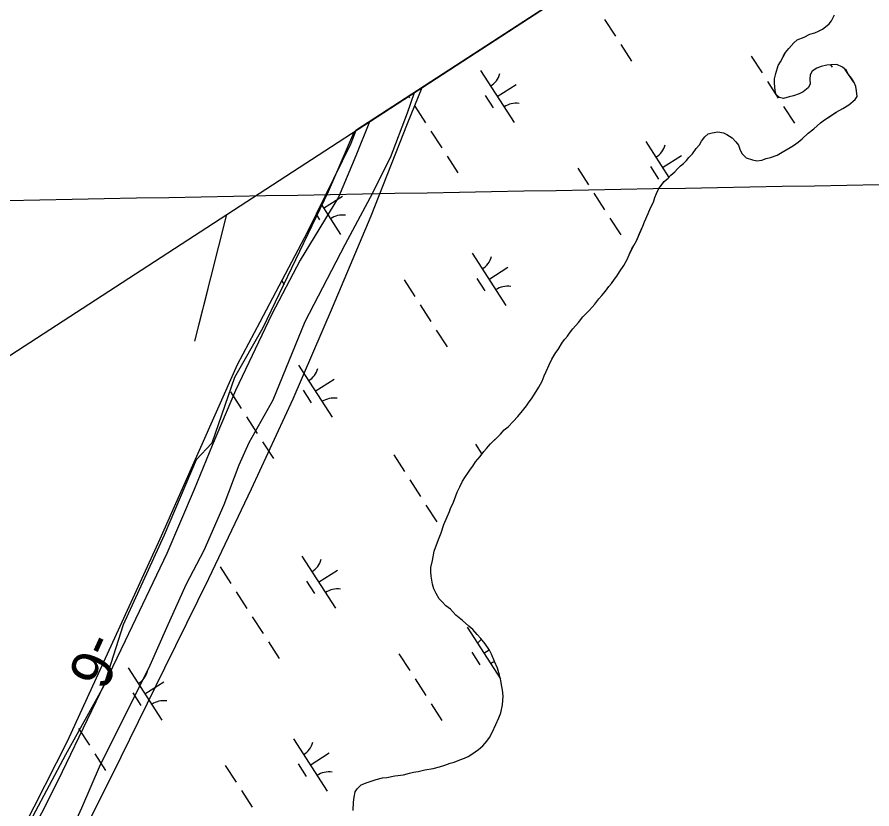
# Model space of a CAD drawing. Extents: x 3937982 to 3958556, y 219448 to 241894.
# Drawn here: x 3943922 to 3944611, y 235847 to 236485 of the extents above; entities that cross this region are included whole.
import ezdxf

# ---------------------------------------------------------------- set-up
doc = ezdxf.new("R2010")
doc.units = 0
for name, color, linetype in [('V-GRID-FRAM', 7, 'Continuous'), ('V-GRID-MAJR', 7, 'Continuous'), ('V-RIVR-EDGE', 7, 'Continuous'), ('V-RIVR-JETY', 7, 'Continuous'), ('V-RIVR-RANG', 7, 'Continuous'), ('V-RRAP-FSHR', 7, 'Continuous'), ('V-TOPO-MINR', 7, 'Continuous'), ('V-TOPO-SHOR', 7, 'Continuous'), ('V-WETL-SWMP', 7, 'Continuous')]:
    doc.layers.add(name, color=color, linetype=linetype)

msp = doc.modelspace()

# ---------------------------------------------------------------- linework, layer by layer
at = {"layer": 'V-GRID-FRAM'}
msp.add_lwpolyline([(3948998.173, 239513.74), (3957109.469, 226912.286), (3949780.097, 222173.81), (3941699.799, 234772.334), (3948998.173, 239513.74)], dxfattribs=at)
at = {"layer": 'V-GRID-MAJR'}
msp.add_spline([(3942640.453, 236314.075), (3945968.142, 236374.431), (3951288.627, 236471.56), (3951347.833, 236472.645)], degree=3, dxfattribs=at)
at = {"layer": 'V-RIVR-EDGE'}
msp.add_lwpolyline([(3944193.63, 236392.457), (3944193.155, 236391.169), (3944172.689, 236343.94), (3944119.949, 236234.524), (3944097.121, 236194.379), (3944079.017, 236141.639), (3944066.422, 236128.257), (3944040.446, 236067.646), (3944007.385, 235995.227), (3943991.642, 235945.636), (3943960.942, 235890.535), (3943855.463, 235692.957), (3943812.956, 235631.558), (3943768.875, 235583.541), (3943727.155, 235505.612), (3943670.48, 235374.156), (3943636.632, 235260.018), (3943585.466, 235124.626), (3943579.956, 235075.035), (3943597.274, 234983.724), (3943619.314, 234871.947)], dxfattribs=at)
at = {"layer": 'V-RIVR-JETY'}
for points in [[(3943918.966, 235747.869), (3943940.493, 235779.634), (3943961.753, 235820.78), (3943974.23, 235847.974), (3943989.155, 235882.951), (3944009.623, 235923.326), (3944029.298, 235962.932), (3944042.598, 235993.238), (3944058.298, 236027.817), (3944072.734, 236055.375), (3944088.858, 236092.29), (3944101.007, 236124.177), (3944109.06, 236142.048), (3944128.278, 236176.577), (3944154.126, 236239.551), (3944186.216, 236301.659), (3944206.653, 236339.69), (3944222.709, 236371.526), (3944236.476, 236407.692), (3944242.031, 236423.901)], [(3944205.869, 236400.408), (3944194.979, 236373.066), (3944180.859, 236339.641), (3944150.089, 236288.851), (3944127.236, 236245.38), (3944097.892, 236184.016), (3944079.325, 236139.707), (3944064.786, 236104.334), (3944042.604, 236052.647), (3944009.232, 235982.349), (3943954.976, 235869.723), (3943928.492, 235817.704), (3943901.241, 235766.865)]]:
    msp.add_lwpolyline(points, dxfattribs=at)
at = {"layer": 'V-RRAP-FSHR'}
msp.add_lwpolyline([(3943648.444, 234864.923), (3943633.272, 234943.444), (3943617.876, 235021.948), (3943622.994, 235100.327), (3943650.171, 235175.566), (3943678.906, 235250.224), (3943708.387, 235324.593), (3943738.82, 235398.878), (3943769.606, 235472.399), (3943805.37, 235543.862), (3943853.205, 235607.915), (3943894.849, 235676.646), (3943933.18, 235746.524), (3943970.3, 235817.305), (3944005.82, 235888.983), (3944041.119, 235960.773), (3944076.417, 236032.566), (3944110.874, 236104.758), (3944144.447, 236177.374), (3944176.138, 236250.819), (3944207.167, 236324.555), (3944236.607, 236398.941), (3944248.265, 236427.951)], dxfattribs=at)
at = {"layer": 'V-TOPO-MINR'}
for points in [[(3944065.36, 236223.83), (3944091.072, 236325.83)], [(3944065.36, 236223.83), (3944075.96, 236265.882)]]:
    msp.add_lwpolyline(points, dxfattribs=at)
at = {"layer": 'V-TOPO-SHOR'}
for points in [[(3944517.978, 236369.099), (3944521.83, 236369.398), (3944525.346, 236370.75), (3944528.859, 236371.754), (3944534.128, 236373.433), (3944538.359, 236375.825), (3944544.706, 236379.589), (3944547.528, 236381.301), (3944551.063, 236384.054), (3944554.248, 236386.811), (3944559.206, 236391.294), (3944563.8, 236394.73), (3944569.11, 236399.559), (3944572.293, 236401.966), (3944576.528, 236404.708), (3944581.82, 236408.136), (3944587.108, 236411.215), (3944592.044, 236413.949), (3944597.002, 236418.432), (3944598.782, 236420.857), (3944598.143, 236425.413), (3944597.489, 236428.92), (3944596.131, 236432.088), (3944594.079, 236435.612), (3944591.669, 236438.445), (3944589.961, 236441.615), (3944586.85, 236444.456), (3944582.33, 236446.614), (3944577.429, 236446.33), (3944574.275, 236446.022), (3944569.714, 236445.031), (3944566.198, 236443.679), (3944562.319, 236441.281), (3944560.877, 236438.152), (3944560.482, 236434.658), (3944560.779, 236430.808), (3944559.337, 236427.676), (3944555.1, 236424.586), (3944551.927, 236422.878), (3944547.356, 236421.188), (3944543.85, 236420.535), (3944539.283, 236419.196), (3944536.146, 236419.937), (3944533.379, 236422.423), (3944532.721, 236425.581), (3944532.101, 236431.537), (3944532.148, 236435.035), (3944533.252, 236439.219), (3944535.089, 236445.84), (3944536.875, 236448.617), (3944539.39, 236453.481), (3944540.825, 236456.26), (3944543.666, 236459.371), (3944547.573, 236463.869), (3944550.404, 236466.279), (3944556.034, 236468.655), (3944560.613, 236471.043), (3944564.476, 236472.04), (3944567.642, 236473.4), (3944570.812, 236475.106), (3944573.284, 236476.822), (3944576.116, 236479.235), (3944577.896, 236481.66), (3944580.411, 236486.524)], [(3944260.606, 236061.836), (3944262.049, 236065.316), (3944263.506, 236069.496), (3944265.693, 236076.113), (3944268.574, 236082.371), (3944270.379, 236086.547), (3944271.47, 236089.681), (3944272.912, 236092.81), (3944274.356, 236096.289), (3944276.535, 236102.208), (3944278.687, 236106.378), (3944280.848, 236110.898), (3944283.347, 236114.713), (3944285.132, 236117.488), (3944287.275, 236120.609), (3944289.054, 236123.034), (3944291.201, 236126.504), (3944295.108, 236131.001), (3944297.957, 236134.81), (3944300.089, 236137.231), (3944303.288, 236141.038), (3944308.959, 236146.562), (3944311.439, 236148.976), (3944314.286, 236152.437), (3944317.466, 236154.846), (3944321.72, 236158.987), (3944325.273, 236163.138), (3944329.181, 236167.634), (3944332.386, 236171.789), (3944334.524, 236174.91), (3944336.308, 236177.335), (3944338.806, 236181.15), (3944342.378, 236186.701), (3944344.891, 236191.567), (3944346.697, 236195.74), (3944348.141, 236199.22), (3944350.664, 236204.784), (3944352.825, 236209.304), (3944356.042, 236214.508), (3944357.822, 236216.933), (3944361.4, 236222.835), (3944363.182, 236225.26), (3944365.314, 236227.681), (3944367.093, 236230.106), (3944369.59, 236233.571), (3944374.206, 236238.759), (3944377.766, 236243.258), (3944382.732, 236248.442), (3944385.216, 236251.206), (3944387.348, 236253.627), (3944390.551, 236257.785), (3944393.037, 236260.549), (3944395.882, 236264.01), (3944398.733, 236267.822), (3944400.863, 236270.243), (3944403.357, 236273.708), (3944405.139, 236276.133), (3944407.285, 236279.604), (3944410.853, 236284.804), (3944413.72, 236290.014), (3944415.531, 236294.538), (3944417.325, 236298.013), (3944418.76, 236300.793), (3944420.911, 236304.612), (3944423.44, 236310.527), (3944425.965, 236316.441), (3944427.411, 236319.921), (3944430.299, 236326.53), (3944432.107, 236331.054), (3944434.616, 236335.568), (3944435.718, 236339.401), (3944437.158, 236342.533), (3944438.962, 236346.707), (3944441.098, 236349.478), (3944443.234, 236352.246), (3944446.419, 236355.003), (3944448.551, 236357.426), (3944451.735, 236360.18), (3944453.867, 236362.601), (3944456.347, 236365.018), (3944458.819, 236366.734), (3944461.301, 236369.151), (3944463.083, 236371.576), (3944465.924, 236374.686), (3944469.127, 236378.844), (3944471.617, 236381.959), (3944473.403, 236384.734), (3944475.897, 236388.199), (3944478.73, 236390.612), (3944481.892, 236391.619), (3944486.449, 236392.258), (3944490.985, 236391.498), (3944493.766, 236390.063), (3944497.932, 236387.558), (3944501.037, 236384.367), (3944503.099, 236381.541), (3944504.447, 236377.674), (3944506.155, 236374.504), (3944509.261, 236371.313), (3944514.49, 236369.845), (3944517.978, 236369.099)], [(3944192.665, 235845.823), (3944193.104, 235852.465), (3944193.509, 235856.657), (3944194.265, 235860.845), (3944196.046, 235863.272), (3944199.235, 235866.379), (3944204.161, 235868.413), (3944211.189, 235870.768), (3944216.455, 235872.097), (3944219.959, 235872.4), (3944226.273, 235873.717), (3944233.283, 235874.673), (3944238.198, 235876.009), (3944241.356, 235876.664), (3944245.213, 235877.313), (3944250.478, 235878.644), (3944257.138, 235879.605), (3944262.404, 235880.934), (3944266.621, 235882.278), (3944270.841, 235883.971), (3944274, 235884.629), (3944278.575, 235886.669), (3944282.439, 235888.016), (3944285.257, 235889.378), (3944288.428, 235891.084), (3944293.726, 235894.863), (3944297.267, 235897.965), (3944300.466, 235901.77), (3944302.602, 235904.541), (3944304.756, 235908.711), (3944307.638, 235914.972), (3944310.159, 235920.534), (3944311.611, 235924.364), (3944313.098, 235930.991), (3944313.54, 235937.983), (3944312.905, 235942.89), (3944312.262, 235947.097), (3944311.609, 235950.605), (3944310.616, 235954.816), (3944308.94, 235960.435), (3944306.561, 235965.715), (3944304.191, 235971.693), (3944302.483, 235974.866), (3944299.057, 235980.16), (3944295.612, 235984.403), (3944292.507, 235987.594), (3944289.06, 235991.487), (3944285.95, 235994.328), (3944280.762, 235998.944), (3944275.57, 236003.212), (3944271.083, 236007.82), (3944267.274, 236010.669), (3944264.517, 236013.853), (3944262.101, 236016.334), (3944259.709, 236020.565), (3944257.661, 236024.44), (3944256.657, 236027.952), (3944255.694, 236034.612), (3944255.391, 236038.114), (3944255.438, 236041.612), (3944256.563, 236047.197), (3944258.06, 236054.523), (3944260.606, 236061.836)]]:
    msp.add_lwpolyline(points, dxfattribs=at)
at = {"layer": 'V-WETL-SWMP'}
for p, q in [((3944595.694, 236653.659), (3944194.946, 236393.312)), ((3944577.897, 236481.659), (3944580.411, 236486.524)), ((3944395.285, 236482.903), (3944403.945, 236469.449)), ((3944573.285, 236476.822), (3944576.116, 236479.234)), ((3944576.116, 236479.234), (3944577.897, 236481.659)), ((3944560.613, 236471.043), (3944564.475, 236472.041)), ((3944564.475, 236472.041), (3944567.642, 236473.399)), ((3944567.642, 236473.399), (3944570.813, 236475.106)), ((3944568.299, 236474.561), (3944568.686, 236473.961)), ((3944570.813, 236475.106), (3944573.285, 236476.822)), ((3944547.573, 236463.869), (3944550.404, 236466.28)), ((3944550.404, 236466.28), (3944556.033, 236468.655)), ((3944556.033, 236468.655), (3944560.613, 236471.043)), ((3944408.275, 236462.722), (3944416.935, 236449.269)), ((3944540.825, 236456.261), (3944543.665, 236459.372)), ((3944543.665, 236459.372), (3944547.573, 236463.869)), ((3944513.433, 236453.164), (3944522.093, 236439.71)), ((3944536.875, 236448.617), (3944540.825, 236456.261)), ((3944533.252, 236439.218), (3944535.089, 236445.841)), ((3944535.089, 236445.841), (3944536.875, 236448.617)), ((3944569.714, 236445.032), (3944566.198, 236443.68)), ((3944574.276, 236446.022), (3944569.714, 236445.032)), ((3944577.429, 236446.33), (3944574.276, 236446.022)), ((3944577.303, 236446.318), (3944578.59, 236444.318)), ((3944582.33, 236446.614), (3944577.429, 236446.33)), ((3944586.85, 236444.455), (3944582.33, 236446.614)), ((3944589.961, 236441.615), (3944586.85, 236444.455)), ((3944295.303, 236441.83), (3944322.365, 236399.787)), ((3944532.147, 236435.035), (3944533.252, 236439.218)), ((3944560.877, 236438.152), (3944560.481, 236434.659)), ((3944562.318, 236441.282), (3944560.877, 236438.152)), ((3944566.198, 236443.68), (3944562.318, 236441.282)), ((3944588.857, 236442.623), (3944595.362, 236432.518)), ((3944591.668, 236438.444), (3944589.961, 236441.615)), ((3944594.08, 236435.613), (3944591.668, 236438.444)), ((3944308.834, 236420.808), (3944323.969, 236430.551)), ((3944526.423, 236432.983), (3944535.083, 236419.529)), ((3944532.1, 236431.537), (3944532.147, 236435.035)), ((3944532.721, 236425.581), (3944532.1, 236431.537)), ((3944560.779, 236430.807), (3944559.338, 236427.677)), ((3944560.481, 236434.659), (3944560.779, 236430.807)), ((3944596.132, 236432.087), (3944594.08, 236435.613)), ((3944597.49, 236428.92), (3944596.132, 236432.087)), ((3944533.379, 236422.424), (3944532.721, 236425.581)), ((3944555.099, 236424.585), (3944551.928, 236422.877)), ((3944559.338, 236427.677), (3944555.099, 236424.585)), ((3944598.143, 236425.413), (3944597.49, 236428.92)), ((3944598.782, 236420.857), (3944598.143, 236425.413)), ((3944237.388, 236420.884), (3944238.098, 236419.781)), ((3944299.099, 236421.678), (3944305.594, 236411.587)), ((3944536.145, 236419.938), (3944533.379, 236422.424)), ((3944539.284, 236419.196), (3944536.145, 236419.938)), ((3944543.85, 236420.535), (3944539.284, 236419.196)), ((3944547.357, 236421.189), (3944543.85, 236420.535)), ((3944551.928, 236422.877), (3944547.357, 236421.189)), ((3944592.043, 236413.949), (3944597.001, 236418.431)), ((3944597.001, 236418.431), (3944598.782, 236420.857)), ((3944242.428, 236413.054), (3944251.088, 236399.601)), ((3944539.413, 236412.802), (3944548.073, 236399.349)), ((3944581.82, 236408.137), (3944587.109, 236411.215)), ((3944587.109, 236411.215), (3944592.043, 236413.949)), ((3944572.292, 236401.965), (3944581.82, 236408.137)), ((3944563.8, 236394.731), (3944569.111, 236399.559)), ((3944569.111, 236399.559), (3944572.292, 236401.965)), ((3944194.946, 236393.312), (3944190.943, 236382.957)), ((3944255.418, 236392.874), (3944264.078, 236379.42)), ((3944475.898, 236388.2), (3944478.729, 236390.611)), ((3944478.729, 236390.611), (3944481.891, 236391.619)), ((3944481.891, 236391.619), (3944486.448, 236392.258)), ((3944486.448, 236392.258), (3944490.986, 236391.498)), ((3944490.986, 236391.498), (3944493.766, 236390.062)), ((3944493.766, 236390.062), (3944497.931, 236387.558)), ((3944554.248, 236386.811), (3944559.206, 236391.293)), ((3944559.206, 236391.293), (3944563.8, 236394.731)), ((3944190.943, 236382.957), (3944156, 236311.827)), ((3944428.432, 236384.531), (3944447.008, 236355.673)), ((3944469.127, 236378.843), (3944471.617, 236381.959)), ((3944471.617, 236381.959), (3944473.403, 236384.734)), ((3944473.403, 236384.734), (3944475.898, 236388.2)), ((3944497.931, 236387.558), (3944501.037, 236384.368)), ((3944501.037, 236384.368), (3944503.099, 236381.542)), ((3944547.528, 236381.302), (3944551.063, 236384.054)), ((3944551.063, 236384.054), (3944554.248, 236386.811)), ((3944465.923, 236374.687), (3944469.127, 236378.843)), ((3944503.099, 236381.542), (3944504.447, 236377.675)), ((3944504.447, 236377.675), (3944506.154, 236374.504)), ((3944534.129, 236373.433), (3944538.359, 236375.826)), ((3944538.359, 236375.826), (3944544.706, 236379.59)), ((3944544.706, 236379.59), (3944547.528, 236381.302)), ((3944268.407, 236372.693), (3944277.067, 236359.239)), ((3944441.963, 236363.51), (3944457.099, 236373.252)), ((3944458.82, 236366.735), (3944461.301, 236369.151)), ((3944461.301, 236369.151), (3944463.083, 236371.576)), ((3944463.083, 236371.576), (3944465.923, 236374.687)), ((3944506.154, 236374.504), (3944509.261, 236371.314)), ((3944509.261, 236371.314), (3944514.489, 236369.845)), ((3944514.489, 236369.845), (3944517.978, 236369.099)), ((3944517.978, 236369.099), (3944521.83, 236369.398)), ((3944521.83, 236369.398), (3944525.347, 236370.751)), ((3944525.347, 236370.751), (3944528.859, 236371.754)), ((3944528.859, 236371.754), (3944534.129, 236373.433)), ((3944373.566, 236363.134), (3944382.226, 236349.681)), ((3944432.228, 236364.379), (3944438.723, 236354.289)), ((3944451.736, 236360.181), (3944453.867, 236362.602)), ((3944453.867, 236362.602), (3944456.348, 236365.018)), ((3944456.348, 236365.018), (3944458.82, 236366.735)), ((3944443.234, 236352.247), (3944446.419, 236355.004)), ((3944446.419, 236355.004), (3944448.551, 236357.425)), ((3944448.551, 236357.425), (3944451.736, 236360.181)), ((3944438.962, 236346.706), (3944443.234, 236352.247)), ((3944386.556, 236342.954), (3944395.216, 236329.5)), ((3944435.717, 236339.402), (3944437.158, 236342.532)), ((3944437.158, 236342.532), (3944438.962, 236346.706)), ((3944166.893, 236334.001), (3944182.498, 236309.757)), ((3944168.967, 236330.779), (3944184.102, 236340.521)), ((3944432.107, 236331.053), (3944434.616, 236335.568)), ((3944434.616, 236335.568), (3944435.717, 236339.402)), ((3944430.298, 236326.529), (3944432.107, 236331.053)), ((3944162.921, 236325.916), (3944165.726, 236321.558)), ((3944399.546, 236322.773), (3944408.206, 236309.319)), ((3944425.966, 236316.441), (3944427.412, 236319.92)), ((3944427.412, 236319.92), (3944430.298, 236326.529)), ((3944420.911, 236304.613), (3944425.966, 236316.441)), ((3944156, 236311.827), (3944117.718, 236239.083)), ((3944415.53, 236294.538), (3944418.761, 236300.793)), ((3944418.761, 236300.793), (3944420.911, 236304.613)), ((3944288.565, 236294.502), (3944315.627, 236252.459)), ((3944413.72, 236290.014), (3944415.53, 236294.538)), ((3944410.852, 236284.804), (3944413.72, 236290.014)), ((3944302.096, 236273.48), (3944317.231, 236283.223)), ((3944405.14, 236276.133), (3944407.285, 236279.603)), ((3944407.285, 236279.603), (3944410.852, 236284.804)), ((3944135.204, 236272.31), (3944137.2, 236269.21)), ((3944233.699, 236273.105), (3944242.359, 236259.651)), ((3944292.361, 236274.35), (3944298.856, 236264.259)), ((3944400.863, 236270.242), (3944403.358, 236273.708)), ((3944403.358, 236273.708), (3944405.14, 236276.133)), ((3944395.883, 236264.011), (3944398.732, 236267.821)), ((3944398.732, 236267.821), (3944400.863, 236270.242)), ((3944390.552, 236257.784), (3944393.038, 236260.55)), ((3944393.038, 236260.55), (3944395.883, 236264.011)), ((3944246.689, 236252.924), (3944255.349, 236239.47)), ((3944382.731, 236248.441), (3944385.217, 236251.207)), ((3944385.217, 236251.207), (3944387.348, 236253.628)), ((3944387.348, 236253.628), (3944390.552, 236257.784)), ((3944377.765, 236243.259), (3944382.731, 236248.441)), ((3944117.718, 236239.083), (3944099.296, 236204.775)), ((3944369.589, 236233.572), (3944374.206, 236238.758)), ((3944374.206, 236238.758), (3944377.765, 236243.259)), ((3944259.678, 236232.743), (3944268.338, 236219.29)), ((3944367.094, 236230.106), (3944369.589, 236233.572)), ((3944361.4, 236222.835), (3944363.182, 236225.26)), ((3944363.182, 236225.26), (3944365.313, 236227.681)), ((3944365.313, 236227.681), (3944367.094, 236230.106)), ((3944356.042, 236214.509), (3944357.823, 236216.934)), ((3944357.823, 236216.934), (3944361.4, 236222.835)), ((3944352.824, 236209.304), (3944356.042, 236214.509)), ((3944099.296, 236204.775), (3944037.173, 236064.347)), ((3944148.697, 236204.472), (3944175.76, 236162.429)), ((3944348.142, 236199.22), (3944350.665, 236204.784)), ((3944350.665, 236204.784), (3944352.824, 236209.304)), ((3944346.697, 236195.741), (3944348.142, 236199.22)), ((3944162.229, 236183.451), (3944177.364, 236193.193)), ((3944342.378, 236186.701), (3944344.892, 236191.566)), ((3944344.892, 236191.566), (3944346.697, 236195.741)), ((3944093.831, 236183.075), (3944102.491, 236169.622)), ((3944152.493, 236184.32), (3944158.988, 236174.23)), ((3944338.806, 236181.151), (3944342.378, 236186.701)), ((3944334.525, 236174.91), (3944336.307, 236177.336)), ((3944336.307, 236177.336), (3944338.806, 236181.151)), ((3944329.181, 236167.634), (3944332.385, 236171.79)), ((3944332.385, 236171.79), (3944334.525, 236174.91)), ((3944106.821, 236162.895), (3944115.481, 236149.441)), ((3944321.719, 236158.987), (3944325.273, 236163.138)), ((3944325.273, 236163.138), (3944329.181, 236167.634)), ((3944314.285, 236152.438), (3944317.466, 236154.845)), ((3944317.466, 236154.845), (3944321.719, 236158.987)), ((3944303.288, 236141.038), (3944311.44, 236148.977)), ((3944311.44, 236148.977), (3944314.285, 236152.438)), ((3944119.811, 236142.714), (3944128.471, 236129.26)), ((3944300.089, 236137.232), (3944303.288, 236141.038)), ((3944291.263, 236140.782), (3944296.426, 236132.762)), ((3944295.108, 236131.001), (3944297.958, 236134.811)), ((3944297.958, 236134.811), (3944300.089, 236137.232)), ((3944225.398, 236132.187), (3944234.058, 236118.733)), ((3944291.2, 236126.504), (3944295.108, 236131.001)), ((3944285.133, 236117.488), (3944287.274, 236120.609)), ((3944287.274, 236120.609), (3944289.055, 236123.034)), ((3944289.055, 236123.034), (3944291.2, 236126.504)), ((3944280.847, 236110.898), (3944283.347, 236114.713)), ((3944283.347, 236114.713), (3944285.133, 236117.488)), ((3944238.388, 236112.007), (3944247.048, 236098.553)), ((3944278.688, 236106.378), (3944280.847, 236110.898)), ((3944274.356, 236096.29), (3944276.534, 236102.209)), ((3944276.534, 236102.209), (3944278.688, 236106.378)), ((3944271.47, 236089.681), (3944272.911, 236092.81)), ((3944272.911, 236092.81), (3944274.356, 236096.29)), ((3944251.378, 236091.826), (3944260.038, 236078.372)), ((3944268.574, 236082.372), (3944270.379, 236086.547)), ((3944270.379, 236086.547), (3944271.47, 236089.681)), ((3944265.692, 236076.113), (3944268.574, 236082.372)), ((3944263.505, 236069.495), (3944265.692, 236076.113)), ((3944260.605, 236061.836), (3944262.05, 236065.316)), ((3944262.05, 236065.316), (3944263.505, 236069.495)), ((3944037.173, 236064.347), (3943962.314, 235901.421)), ((3944258.059, 236054.523), (3944260.605, 236061.836)), ((3944256.562, 236047.196), (3944258.059, 236054.523)), ((3944151.396, 236050.753), (3944178.458, 236008.71)), ((3944255.438, 236041.613), (3944256.562, 236047.196)), ((3944085.531, 236042.158), (3944094.191, 236028.704)), ((3944164.927, 236029.731), (3944180.063, 236039.474)), ((3944255.392, 236038.115), (3944255.438, 236041.613)), ((3944255.695, 236034.612), (3944255.392, 236038.115)), ((3944256.657, 236027.952), (3944255.695, 236034.612)), ((3944155.192, 236030.6), (3944161.687, 236020.51)), ((3944257.66, 236024.44), (3944256.657, 236027.952)), ((3944259.708, 236020.564), (3944257.66, 236024.44)), ((3944098.521, 236021.977), (3944107.181, 236008.523)), ((3944262.1, 236016.334), (3944259.708, 236020.564)), ((3944264.517, 236013.853), (3944262.1, 236016.334)), ((3944267.273, 236010.668), (3944264.517, 236013.853)), ((3944271.084, 236007.819), (3944267.273, 236010.668)), ((3944275.571, 236003.211), (3944271.084, 236007.819)), ((3944280.762, 235998.944), (3944275.571, 236003.211)), ((3944111.511, 236001.796), (3944120.171, 235988.342)), ((3944285.949, 235994.327), (3944280.762, 235998.944)), ((3944284.525, 235993.454), (3944311.321, 235951.826)), ((3944289.06, 235991.487), (3944285.949, 235994.327)), ((3944292.507, 235987.593), (3944289.06, 235991.487)), ((3944295.613, 235984.403), (3944292.507, 235987.593)), ((3944299.056, 235980.159), (3944295.613, 235984.403)), ((3944124.501, 235981.616), (3944133.161, 235968.162)), ((3944302.484, 235974.865), (3944299.056, 235980.159)), ((3944229.659, 235972.057), (3944238.319, 235958.603)), ((3944288.321, 235973.302), (3944294.816, 235963.211)), ((3944298.056, 235972.433), (3944302.293, 235975.16)), ((3944304.191, 235971.694), (3944302.484, 235974.865)), ((3944306.561, 235965.715), (3944304.191, 235971.694)), ((3944308.94, 235960.435), (3944306.561, 235965.715)), ((3944011.529, 235960.723), (3944038.591, 235918.68)), ((3944310.615, 235954.815), (3944308.94, 235960.435)), ((3944025.06, 235939.702), (3944040.196, 235949.444)), ((3944242.649, 235951.876), (3944251.309, 235938.423)), ((3944311.609, 235950.604), (3944310.615, 235954.815)), ((3944312.262, 235947.097), (3944311.609, 235950.604)), ((3944312.906, 235942.89), (3944312.262, 235947.097)), ((3944313.541, 235937.983), (3944312.906, 235942.89)), ((3944015.325, 235940.571), (3944021.82, 235930.48)), ((3944313.098, 235930.992), (3944313.541, 235937.983)), ((3944255.639, 235931.696), (3944264.299, 235918.242)), ((3944311.611, 235924.364), (3944313.098, 235930.992)), ((3944310.16, 235920.535), (3944311.611, 235924.364)), ((3944304.756, 235908.712), (3944307.638, 235914.971)), ((3944307.638, 235914.971), (3944310.16, 235920.535)), ((3943971.644, 235911.767), (3943980.304, 235898.313)), ((3944302.601, 235904.542), (3944304.756, 235908.712)), ((3943962.314, 235901.421), (3943897.877, 235774.016)), ((3944144.658, 235903.425), (3944171.72, 235861.381)), ((3944297.266, 235897.965), (3944300.465, 235901.771)), ((3944300.465, 235901.771), (3944302.601, 235904.542)), ((3944288.428, 235891.085), (3944293.726, 235894.863)), ((3944293.726, 235894.863), (3944297.266, 235897.965)), ((3943984.634, 235891.586), (3943993.293, 235878.132)), ((3944158.189, 235882.403), (3944173.325, 235892.145)), ((3944273.999, 235884.629), (3944278.574, 235886.668)), ((3944278.574, 235886.668), (3944282.44, 235888.016)), ((3944282.44, 235888.016), (3944285.257, 235889.378)), ((3944285.257, 235889.378), (3944288.428, 235891.085)), ((3944089.792, 235882.028), (3944098.452, 235868.574)), ((3944148.454, 235883.272), (3944154.949, 235873.182)), ((3944250.479, 235878.644), (3944257.139, 235879.605)), ((3944257.139, 235879.605), (3944262.404, 235880.934)), ((3944262.404, 235880.934), (3944266.62, 235882.278)), ((3944266.62, 235882.278), (3944270.841, 235883.971)), ((3944270.841, 235883.971), (3944273.999, 235884.629)), ((3944216.455, 235872.098), (3944219.958, 235872.401)), ((3944219.958, 235872.401), (3944226.273, 235873.717)), ((3944226.273, 235873.717), (3944233.283, 235874.673)), ((3944233.283, 235874.673), (3944238.198, 235876.008)), ((3944238.198, 235876.008), (3944241.356, 235876.665)), ((3944241.356, 235876.665), (3944245.213, 235877.314)), ((3944245.213, 235877.314), (3944250.479, 235878.644)), ((3944196.046, 235863.272), (3944199.236, 235866.378)), ((3944199.236, 235866.378), (3944204.161, 235868.412)), ((3944204.161, 235868.412), (3944211.19, 235870.768)), ((3944211.19, 235870.768), (3944216.455, 235872.098)), ((3944102.782, 235861.847), (3944111.442, 235848.393)), ((3944193.51, 235856.658), (3944194.265, 235860.846)), ((3944194.265, 235860.846), (3944196.046, 235863.272)), ((3944192.666, 235845.824), (3944193.104, 235852.465)), ((3944193.104, 235852.465), (3944193.51, 235856.658))]:
    msp.add_line(p, q, dxfattribs=at)
for centre, start, end in [((3944294.084, 236444.163), 301.99668, 343.540338), ((3944323.984, 236397.711), 81.996677, 123.540335), ((3944427.213, 236386.864), 301.99668, 343.540338), ((3944184.116, 236307.681), 81.996677, 123.540335), ((3944287.346, 236296.835), 301.99668, 343.540338), ((3944317.246, 236250.383), 81.996677, 123.540335), ((3944147.478, 236206.805), 301.99668, 343.540338), ((3944177.378, 236160.353), 81.996677, 123.540335), ((3944150.177, 236053.086), 301.99668, 343.540338), ((3944180.077, 236006.634), 81.996677, 123.540335), ((3944283.306, 235995.787), 301.99668, 316.830041), ((3944313.206, 235949.335), 112.075209, 123.540335), ((3944010.31, 235963.056), 301.99668, 343.540338), ((3944040.21, 235916.604), 81.996677, 123.540335), ((3944143.439, 235905.757), 301.99668, 343.540338), ((3944173.339, 235859.306), 81.996677, 123.540335)]:
    msp.add_arc(centre, 17.623, start, end, dxfattribs=at)

# ---------------------------------------------------------------- texts
at = {"layer": 'V-RIVR-RANG'}
msp.add_text('-6', height=33.5, rotation=245.548326, dxfattribs=at).set_placement((3943978.961, 235991.385))

doc.saveas('drawing.dxf')
